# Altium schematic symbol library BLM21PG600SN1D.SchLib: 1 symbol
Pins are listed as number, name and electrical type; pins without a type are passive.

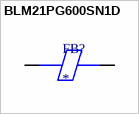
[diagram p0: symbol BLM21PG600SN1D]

## BLM21PG600SN1D
designator FB?
60 Ohms @ 100 MHz 1 Power Line Ferrite Bead 0805 (2012 Metric) 3.5A 20mOhm
footprint BEADC2012X105N
pins: 1, 2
